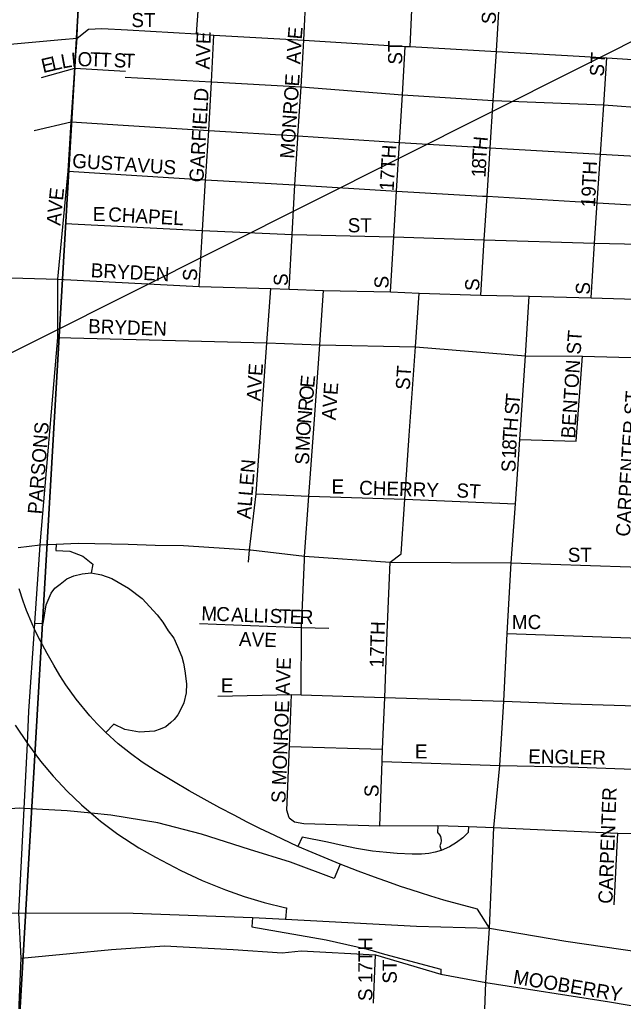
# Model space of a CAD drawing. Extents: x 0 to 34, y -6.2 to 22.
# Drawn here: x 7.636 to 8.04, y 17.461 to 18.119 of the extents above; entities that cross this region are included whole.
import ezdxf

# ---------------------------------------------------------------- set-up
doc = ezdxf.new("R2010")
doc.units = 0
for name, color, linetype in [('GM_X_City_Street', 7, 'Continuous'), ('GM_X_City_Street_Text', 7, 'Continuous'), ('GM_X_Interchange_Ramps', 7, 'Continuous'), ('GM_X_Interstate_Route', 7, 'Continuous'), ('GM_X_Section', 7, 'Continuous'), ('SH_Data', 7, 'Continuous')]:
    doc.layers.add(name, color=color, linetype=linetype)

msp = doc.modelspace()

# ---------------------------------------------------------------- linework, layer by layer
at = {"layer": 'GM_X_City_Street'}
for points in [[(7.9551, 18.098), (7.95711, 18.13186), (7.95913, 18.16569), (7.96159, 18.20031), (7.96364, 18.24118)], [(7.89727, 18.10088), (7.89886, 18.13533), (7.89104, 18.18961), (7.88576, 18.22974)], [(7.82196, 18.03961), (7.82204, 18.04099), (7.82409, 18.07387), (7.82606, 18.10512), (7.82765, 18.138), (7.82188, 18.17931), (7.81592, 18.22114)], [(7.75402, 18.10952), (7.75646, 18.14323), (7.75243, 18.1694), (7.74708, 18.20944)], [(7.66111, 17.931), (7.66112, 17.94502), (7.66814, 18.01739), (7.67004, 18.05035), (7.6725, 18.0863), (7.67405, 18.10652), (7.67528, 18.14902), (7.67557, 18.15804), (7.67636, 18.1991)], [(7.66356, 18.10558), (7.67405, 18.10652), (7.68173, 18.11256), (7.69057, 18.11304), (7.70772, 18.11211), (7.75402, 18.10952), (7.76576, 18.10853), (7.82606, 18.10512), (7.8939, 18.10099), (7.89727, 18.10088), (7.95507, 18.09755), (8.0105, 18.09437), (8.02917, 18.0933), (8.05337, 18.09175), (8.08886, 18.08972), (8.14985, 18.08599), (8.20447, 18.08319), (8.26777, 18.0794), (8.34276, 18.07512), (8.42538, 18.07039)], [(7.18784, 18.03558), (7.30213, 18.0516), (7.39992, 18.06535), (7.4321, 18.07162), (7.58337, 18.09349), (7.6002, 18.09595), (7.6086, 18.09723), (7.62089, 18.10098), (7.63159, 18.10271), (7.66356, 18.10558)], [(7.76026, 18.01379), (7.76224, 18.04467), (7.76401, 18.07726), (7.76576, 18.10853)], [(7.88413, 17.93645), (7.88636, 17.97349), (7.88818, 18.00391), (7.89006, 18.03662), (7.8921, 18.06865), (7.8939, 18.10099)], [(7.94462, 17.9344), (7.94695, 17.9713), (7.94879, 18.00057), (7.9508, 18.03292), (7.95295, 18.06474), (7.95507, 18.09755), (7.9551, 18.098)], [(8.01852, 17.93247), (8.02091, 17.96918), (8.02267, 17.99622), (8.0249, 18.0288), (8.02712, 18.06179), (8.02917, 18.0933)], [(7.65023, 18.0801), (7.6725, 18.0863), (7.70651, 18.08442)], [(7.70635, 18.08043), (7.76401, 18.07726), (7.82409, 18.07387), (7.8921, 18.06865), (7.95295, 18.06474), (8.02712, 18.06179), (8.08638, 18.05732), (8.14784, 18.05376), (8.20184, 18.05052), (8.26562, 18.04728), (8.34076, 18.04298), (8.48824, 18.0351), (8.52845, 18.03276), (8.55595, 18.03062)], [(7.64515, 18.0447), (7.67004, 18.05035), (7.70487, 18.04817), (7.76224, 18.04467)], [(7.76224, 18.04467), (7.82204, 18.04099), (7.89006, 18.03662), (7.9508, 18.03292), (8.0249, 18.0288), (8.08386, 18.02542), (8.14542, 18.02188), (8.19928, 18.01857), (8.2634, 18.01441), (8.33874, 18.01052), (8.42174, 18.00619), (8.48589, 18.00283), (8.52591, 17.99969), (8.55367, 17.99785)], [(7.81606, 17.93838), (7.8181, 17.97501), (7.81996, 18.00819), (7.82196, 18.03961)], [(7.66814, 18.01739), (7.76011, 18.01149), (7.81996, 18.00819), (7.88818, 18.00391), (7.94572, 18.00074)], [(7.75579, 17.94012), (7.75805, 17.9776), (7.76011, 18.01149), (7.76026, 18.01379)], [(7.94572, 18.00074), (7.94879, 18.00057), (8.01512, 17.99666)], [(8.01512, 17.99666), (8.02267, 17.99622), (8.08125, 17.99276), (8.09305, 17.99209), (8.144, 17.98904)], [(7.66599, 17.98241), (7.75805, 17.9776), (7.8181, 17.97501), (7.88636, 17.97349), (7.94695, 17.9713), (8.02091, 17.96918), (8.09133, 17.96766), (8.15922, 17.96516), (8.19504, 17.96522), (8.25994, 17.96268)], [(7.21395, 17.89319), (7.41935, 17.92213), (7.49633, 17.93416), (7.60261, 17.94497), (7.62983, 17.94583), (7.66112, 17.94502)], [(7.66112, 17.94502), (7.75579, 17.94012), (7.80379, 17.9388), (7.81606, 17.93838), (7.83909, 17.93736), (7.88413, 17.93645), (7.90329, 17.93573), (7.94462, 17.9344), (7.97705, 17.93365), (8.01852, 17.93247), (8.05587, 17.93137), (8.08871, 17.93047), (8.10333, 17.93005), (8.15046, 17.92861), (8.15701, 17.92842), (8.19269, 17.92754), (8.25735, 17.92566), (8.328, 17.92274), (8.3878, 17.92201)], [(7.78901, 17.75539), (7.78947, 17.76362), (7.79413, 17.8012), (7.80127, 17.90232), (7.80379, 17.9388)], [(7.82637, 17.75693), (7.82647, 17.75951), (7.8294, 17.79959), (7.83242, 17.84183), (7.83665, 17.90096), (7.83909, 17.93736)], [(7.87682, 17.57879), (7.87856, 17.62185), (7.87866, 17.63008), (7.88027, 17.66467), (7.8819, 17.70821), (7.88383, 17.7555), (7.89123, 17.76097), (7.89371, 17.7976), (7.89666, 17.84023), (7.90078, 17.89965), (7.90329, 17.93573)], [(7.96485, 17.7549), (7.9679, 17.79444), (7.9707, 17.83756), (7.97455, 17.89371), (7.97705, 17.93365)], [(7.63079, 17.35411), (7.63079, 17.35411), (7.63652, 17.49009), (7.63495, 17.5204), (7.63847, 17.59027), (7.64067, 17.63383), (7.64177, 17.65552), (7.64546, 17.71058), (7.64573, 17.71461), (7.64925, 17.76698), (7.6611, 17.90598), (7.66111, 17.931)], [(7.6611, 17.90598), (7.80127, 17.90232), (7.83665, 17.90096), (7.90078, 17.89965), (7.97455, 17.89371), (8.01271, 17.89353), (8.05347, 17.89238), (8.1008, 17.89084), (8.14803, 17.88995), (8.18926, 17.88903), (8.25502, 17.88939), (8.33006, 17.88766), (8.36356, 17.88607)], [(8.00845, 17.83643), (8.01271, 17.89353)], [(7.9707, 17.83756), (8.00845, 17.83643)], [(7.79413, 17.8012), (7.8294, 17.79959), (7.89371, 17.7976), (7.9679, 17.79444)], [(7.63449, 17.76524), (7.64925, 17.76698), (7.6599, 17.76742), (7.6748, 17.76803), (7.70825, 17.7675), (7.72643, 17.76672), (7.74539, 17.76645), (7.78947, 17.76362), (7.79043, 17.76355), (7.82647, 17.75951), (7.88383, 17.7555), (7.96485, 17.7549), (8.04462, 17.75228), (8.05909, 17.75168), (8.10599, 17.74978), (8.17723, 17.7477), (8.19405, 17.74724), (8.24013, 17.74287), (8.31546, 17.74112), (8.38222, 17.73913)], [(7.82428, 17.66653), (7.82451, 17.71171), (7.82637, 17.75693)], [(7.93708, 17.2313), (7.94159, 17.32588), (7.94508, 17.39478), (7.94805, 17.47367), (7.95036, 17.51006), (7.95328, 17.57766), (7.95729, 17.61918), (7.96, 17.66217), (7.96231, 17.70755), (7.96485, 17.7549)], [(7.75595, 17.7142), (7.82451, 17.71171), (7.8428, 17.71115)], [(7.96231, 17.70755), (8.05743, 17.70425), (8.10415, 17.70317), (8.19102, 17.70012), (8.2422, 17.69834), (8.31689, 17.69592), (8.38485, 17.69387)], [(7.76828, 17.66571), (7.8178, 17.66668), (7.82428, 17.66653), (7.88027, 17.66467), (7.96, 17.66217), (8.00462, 17.66056), (8.05587, 17.65895), (8.10282, 17.65755), (8.13492, 17.65641), (8.18799, 17.65467), (8.2392, 17.653), (8.31383, 17.65069), (8.37477, 17.64802)], [(7.81607, 17.58418), (7.8146, 17.58914), (7.81629, 17.63181), (7.8178, 17.66668)], [(7.81629, 17.63181), (7.87866, 17.63008)], [(7.87856, 17.62185), (7.95729, 17.61918), (8.00365, 17.61821), (8.10267, 17.61473)], [(7.81607, 17.58418), (7.81981, 17.5813), (7.82589, 17.58035), (7.87682, 17.57879), (7.91582, 17.579), (7.93634, 17.57827), (7.95328, 17.57766), (8.03648, 17.57384), (8.09778, 17.57275), (8.12855, 17.57147), (8.1636, 17.5695), (8.18246, 17.56853), (8.23352, 17.5669), (8.3063, 17.56527), (8.36939, 17.56364), (8.4092, 17.56248), (8.45241, 17.56102), (8.52926, 17.55843), (8.62789, 17.556), (8.74117, 17.5532), (8.77011, 17.55227), (8.83816, 17.55008), (8.88173, 17.54854), (8.88683, 17.54836)], [(8.03401, 17.52577), (8.03648, 17.57384)], [(7.63652, 17.49009), (7.66914, 17.49319), (7.69701, 17.49577), (7.73261, 17.49835), (7.77854, 17.49577), (7.81156, 17.4937), (7.82424, 17.49501), (7.87402, 17.49234), (7.91778, 17.47933), (7.94805, 17.47367), (8.03087, 17.46069), (8.09284, 17.45035), (8.15077, 17.44037), (8.22291, 17.43128), (8.26486, 17.42935)], [(7.87263, 17.45988), (7.87402, 17.49234)]]:
    msp.add_lwpolyline(points, dxfattribs=at)
at = {"layer": 'GM_X_Interchange_Ramps'}
for points in [[(7.6599, 17.76742), (7.65987, 17.76315), (7.66909, 17.76274), (7.67781, 17.75937), (7.6845, 17.75398), (7.68355, 17.74828)], [(7.64573, 17.71461), (7.65129, 17.7143), (7.65326, 17.72689), (7.65662, 17.73462), (7.6592, 17.73798), (7.66276, 17.74075), (7.66712, 17.74412), (7.67187, 17.7463), (7.67741, 17.74748), (7.68355, 17.74828), (7.69048, 17.74689), (7.6974, 17.74451), (7.70849, 17.73798), (7.71759, 17.73105), (7.72775, 17.72013), (7.73139, 17.71523), (7.73503, 17.70948), (7.73882, 17.70451), (7.74121, 17.69888), (7.74411, 17.69188), (7.74531, 17.68778), (7.74633, 17.68266), (7.74736, 17.67379), (7.74718, 17.66781), (7.74565, 17.66116), (7.74343, 17.65638), (7.74155, 17.65314), (7.73899, 17.65007), (7.73674, 17.64803), (7.73345, 17.64496), (7.72961, 17.6434), (7.72586, 17.64221), (7.71579, 17.64153), (7.70607, 17.64324), (7.69873, 17.64682), (7.6932, 17.64123)], [(7.95036, 17.51006), (7.94239, 17.52277), (7.91986, 17.52893), (7.9112, 17.53155), (7.90424, 17.53373), (7.89796, 17.53576), (7.89081, 17.53814), (7.88401, 17.54048), (7.87341, 17.54426), (7.86243, 17.54835), (7.85844, 17.54982), (7.85028, 17.55312), (7.84238, 17.55633), (7.83156, 17.56089), (7.82206, 17.56494), (7.80665, 17.57213), (7.79661, 17.57696), (7.78795, 17.58127), (7.7792, 17.58576), (7.76977, 17.59075), (7.76118, 17.59544), (7.74911, 17.60226), (7.7387, 17.60838), (7.72629, 17.61587), (7.7176, 17.62145), (7.70973, 17.62712), (7.70155, 17.6337), (7.6932, 17.64123), (7.6874, 17.64706), (7.68246, 17.65243), (7.67341, 17.66348), (7.66657, 17.6731), (7.66256, 17.6794), (7.65849, 17.6864), (7.65387, 17.69428), (7.64764, 17.70591), (7.64546, 17.71058), (7.6438, 17.71412), (7.64012, 17.72301), (7.63781, 17.72927), (7.63509, 17.73759)], [(7.6325, 17.64613), (7.64067, 17.63383), (7.64948, 17.62202), (7.6579, 17.61201), (7.6673, 17.60196), (7.67695, 17.59271), (7.68353, 17.58713), (7.68966, 17.58193), (7.70131, 17.57323), (7.71538, 17.56404), (7.72662, 17.55762), (7.74365, 17.54883), (7.75789, 17.54216), (7.77341, 17.53586), (7.7859, 17.53147), (7.79933, 17.5274), (7.81384, 17.5238), (7.8143, 17.5237), (7.81375, 17.51623)], [(7.85028, 17.55312), (7.84633, 17.54338), (7.81707, 17.55428), (7.78953, 17.56289), (7.75741, 17.57322), (7.72815, 17.58068), (7.6966, 17.58585), (7.68353, 17.58713), (7.66734, 17.58872), (7.63847, 17.59027), (7.63521, 17.59044), (7.60194, 17.58814), (7.56973, 17.58487), (7.56236, 17.58413), (7.54457, 17.58045), (7.52621, 17.57666), (7.48949, 17.56576), (7.45393, 17.55371), (7.4132, 17.53878), (7.38221, 17.52674), (7.35755, 17.51812), (7.35957, 17.50467)], [(7.93634, 17.57827), (7.93615, 17.57432), (7.93247, 17.57072), (7.92839, 17.56754), (7.92367, 17.5647), (7.91811, 17.56216), (7.91397, 17.56099), (7.90973, 17.56012), (7.90479, 17.55963), (7.89857, 17.55978), (7.88857, 17.5602), (7.88134, 17.56077), (7.87194, 17.56183), (7.86129, 17.56349), (7.85158, 17.56544), (7.84188, 17.5678), (7.82483, 17.57106), (7.82206, 17.56494)], [(7.91582, 17.579), (7.91559, 17.57407), (7.91599, 17.57372), (7.91692, 17.57261), (7.91752, 17.57151), (7.91788, 17.57046), (7.91808, 17.56884), (7.91788, 17.56717), (7.91712, 17.56524), (7.91811, 17.56216)], [(7.79169, 17.51739), (7.79122, 17.51095), (7.84104, 17.50227), (7.8687, 17.49598), (7.87999, 17.49265), (7.91785, 17.48269), (7.91778, 17.47933)]]:
    msp.add_lwpolyline(points, dxfattribs=at)
at = {"layer": 'GM_X_Interstate_Route'}
for points in [[(7.4582, 17.51676), (7.50019, 17.51523), (7.52115, 17.51691), (7.5644, 17.519), (7.63495, 17.5204), (7.71155, 17.52027), (7.79169, 17.51739), (7.80051, 17.51693)], [(7.80051, 17.51693), (7.81375, 17.51623), (7.90155, 17.51155), (7.95036, 17.51006), (8.00163, 17.50148), (8.10303, 17.48679), (8.226, 17.47322), (8.30058, 17.46291), (8.43393, 17.45569), (8.52361, 17.45235), (8.55859, 17.45105), (8.58568, 17.45016), (8.76385, 17.44432), (8.87734, 17.44296), (9.00959, 17.43438), (9.04405, 17.43249), (9.07548, 17.43053)]]:
    msp.add_lwpolyline(points, dxfattribs=at)
at = {"layer": 'GM_X_Section'}
for points in [[(6.68124, 18.27598), (6.6863, 18.2758), (7.19351, 18.24276), (7.67976, 18.21035), (7.62278, 17.23025), (6.6036, 17.30139)], [(8.19802, 18.176), (8.1365, 17.19384), (7.62278, 17.23025), (7.67976, 18.21035)]]:
    msp.add_lwpolyline(points, close=True, dxfattribs=at)
at = {"layer": 'SH_Data'}
msp.add_lwpolyline([(10.0459, 19.98884), (6.75174, 17.45513), (10.0459, 19.10806)], close=True, dxfattribs=at)

# ---------------------------------------------------------------- texts
at = {"layer": 'GM_X_City_Street_Text'}
for s, height, rotation, p in [('ST', 0.00947, 86.42621, (7.95446, 18.11556)), ('ST', 0.00947, 0.00001, (7.7104, 18.1139)), ('AVE', 0.00947, 87.9557, (7.76279, 18.08551)), ('E', 0.00947, 84.8847, (7.82452, 18.10541)), ('V', 0.00947, 86.71953, (7.82405, 18.09718)), ('ST', 0.00947, 90, (7.89196, 18.08878)), ('O', 0.00947, 0.29452, (7.67437, 18.08764)), ('T', 0.00947, 357.7556, (7.68259, 18.08769)), ('A', 0.00947, 87.09174, (7.82363, 18.08887)), ('ST', 0.00947, 86.18882, (8.02696, 18.08057)), ('E', 0.00947, 12.98909, (7.65122, 18.08311)), ('L', 0.00947, 12.98909, (7.65771, 18.08461)), ('L', 0.00947, 10.45017, (7.6641, 18.08609)), ('I', 0.00947, 5.37234, (7.67044, 18.08726)), ('T', 0.00947, 357.7556, (7.68925, 18.08743)), ('S', 0.00947, 357.7556, (7.69841, 18.08707)), ('T', 0.00947, 357.7556, (7.70507, 18.08681)), ('MONROE', 0.00947, 86.18446, (7.81946, 18.02553)), ('GARFIELD', 0.00947, 86.67801, (7.75862, 18.00967)), ('H', 0.00947, 84.85701, (7.9486, 18.03122)), ('17TH', 0.00947, 86.42578, (7.88613, 18.00389)), ('T', 0.00947, 87.26718, (7.94829, 18.02466)), ('GUSTAVUS', 0.00947, 356.13378, (7.67052, 18.01973)), ('8', 0.00947, 87.53214, (7.94804, 18.01885)), ('1', 0.00947, 87.56334, (7.94779, 18.01302)), ('19TH', 0.00947, 87.27516, (8.02113, 17.99303)), ('AVE', 0.00947, 84.09694, (7.6628, 17.98063)), ('E', 0.00947, 0.00001, (7.68457, 17.98389)), ('CHAPEL', 0.00947, 356.82196, (7.69467, 17.98389)), ('ST', 0.00947, 0.00001, (7.8554, 17.9764)), ('BRYDEN', 0.00947, 356.98882, (7.68299, 17.94636)), ('S', 0.00947, 90, (7.75446, 17.94378)), ('S', 0.00947, 90, (7.81529, 17.94045)), ('S', 0.00947, 90, (7.88279, 17.93878)), ('S', 0.00947, 90, (7.94362, 17.93712)), ('S', 0.00947, 90, (8.01779, 17.93462)), ('BRYDEN', 0.00947, 357.99152, (7.6813, 17.90886)), ('BENTON ST', 0.00947, 86.23784, (8.00779, 17.83807)), ('AVE', 0.00947, 86.05688, (7.79696, 17.86307)), ('ST', 0.00947, 86.41175, (7.89696, 17.87056)), ('E', 0.00947, 84.93437, (7.83293, 17.87193)), ('O', 0.00947, 84.92476, (7.83219, 17.86363)), ('AVE', 0.00947, 86.05688, (7.84738, 17.85029)), ('T', 0.00947, 85.24089, (7.97048, 17.86032)), ('CARPENTER ST', 0.0094697, 86.03542, (8.04446, 17.77224)), ('R', 0.00947, 84.91769, (7.83153, 17.85616)), ('S', 0.00947, 85.24089, (7.96993, 17.85368)), ('N', 0.00947, 84.96587, (7.8308, 17.84786)), ('PARSONS', 0.00947, 85.46468, (7.65029, 17.78726)), ('O', 0.00947, 85.9533, (7.83021, 17.83959)), ('H', 0.00947, 85.29624, (7.96904, 17.84288)), ('T', 0.00947, 86.20046, (7.9686, 17.83627)), ('M', 0.00947, 87.70428, (7.82982, 17.82968)), ('8', 0.00947, 87.59454, (7.96836, 17.8305)), ('S', 0.00947, 87.7596, (7.82946, 17.82052)), ('1', 0.00947, 87.86111, (7.96814, 17.82468)), ('ALLEN', 0.00947, 85.13341, (7.7903, 17.78398)), ('S', 0.00947, 87.84148, (7.96779, 17.81552)), ('E', 0.00947, 0.00001, (7.84457, 17.8014)), ('CHERRY', 0.00947, 358.25979, (7.86294, 17.80057)), ('ST', 0.00947, 356.42622, (7.92801, 17.79889)), ('ST', 0.00947, 0.00001, (8.0029, 17.75557)), ('M', 0.00947, 357.88699, (7.75714, 17.7164)), ('C', 0.00947, 357.88699, (7.76713, 17.71603)), ('A', 0.00947, 357.87971, (7.77713, 17.71566)), ('L', 0.00947, 357.89449, (7.78546, 17.71535)), ('L', 0.00947, 357.86879, (7.79212, 17.71511)), ('I', 0.00947, 357.91106, (7.79879, 17.71486)), ('S', 0.00947, 357.89609, (7.80295, 17.71471)), ('T', 0.00947, 357.86879, (7.80961, 17.71446)), ('E', 0.00947, 358.09631, (7.81632, 17.71421)), ('R', 0.00947, 359.45971, (7.82323, 17.71398)), ('MC', 0.00947, 0.00001, (7.9654, 17.71056)), ('17TH', 0.00947, 88.21114, (7.87946, 17.68467)), ('AVE', 0.00947, 358.02636, (7.7824, 17.69928)), ('S MONROE AVE', 0.0094697, 87.77437, (7.81362, 17.59378)), ('E', 0.00947, 0.00001, (7.7704, 17.66807)), ('E', 0.00947, 0.00001, (7.9004, 17.62389)), ('ENGLER', 0.00947, 358.95997, (7.97632, 17.62056)), ('S', 0.00947, 90, (7.87612, 17.59795)), ('CARPENTER', 0.00947, 87.87999, (8.03279, 17.52635)), ('S 17TH', 0.00947, 90, (7.87195, 17.46128)), ('ST', 0.00947, 90, (7.88825, 17.47295)), ('MOOBERRY', 0.00947, 350.53723, (7.9657, 17.47304))]:
    msp.add_text(s, height=height, rotation=rotation, dxfattribs=at).set_placement(p)

doc.saveas('drawing.dxf')
